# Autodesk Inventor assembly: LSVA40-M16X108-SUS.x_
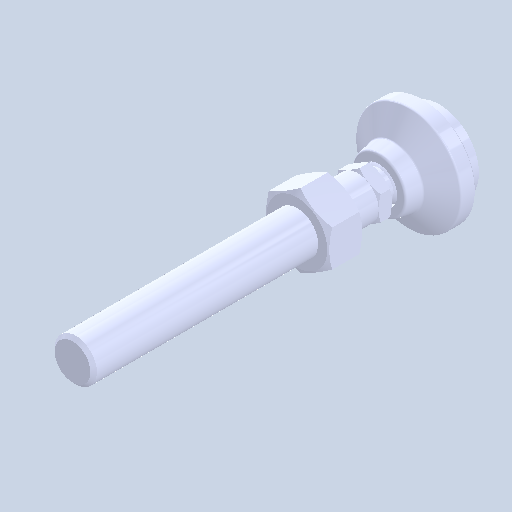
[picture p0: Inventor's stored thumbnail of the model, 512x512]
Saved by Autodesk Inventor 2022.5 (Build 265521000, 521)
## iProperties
Created: 2024-08
Part Number: LSVA40-M16X108-SUS.x_
Document SubType Name: Assembly
Designer: ImaoCorp
Author: ImaoCorp
Sending System: SOLIDWORKS 2022-2022290
MC: AMD64
MC_MODEL: Intel64 Family 6 Model 60 Stepping 3, GenuineIntel
OS: Windows_NT
FRU: Parasolid Version 33.1, build 260,  4-25-2022
FORMAT: text
GUISE: transmit
KEY: FILELSVA40-M16X108-SUS.x_t
DATE: Fri Aug 23 16:07:40 2024
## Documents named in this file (4)
- X:\14_SW2022-Inv2022\06_2024-10新製品(SME)\ELS_データ\l\lsva40-m16x108-sus\LSVA40-M16X108-SUS.x_.iam
- X:\14_SW2022-Inv2022\06_2024-10新製品(SME)\ELS_データ\l\lsva40-m16x108-sus\LSVA40-M16X108-SUS_01.ipt
- X:\14_SW2022-Inv2022\06_2024-10新製品(SME)\ELS_データ\l\lsva40-m16x108-sus\LSVA40-M16X108-SUS_02.ipt
- X:\14_SW2022-Inv2022\06_2024-10新製品(SME)\ELS_データ\l\lsva40-m16x108-sus\LSVA40-M16X108-SUS_03.ipt
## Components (3 placed, 3 different names)
1. LSVA40-M16X108-SUS_01
2. LSVA40-M16X108-SUS_02
3. LSVA40-M16X108-SUS_03
